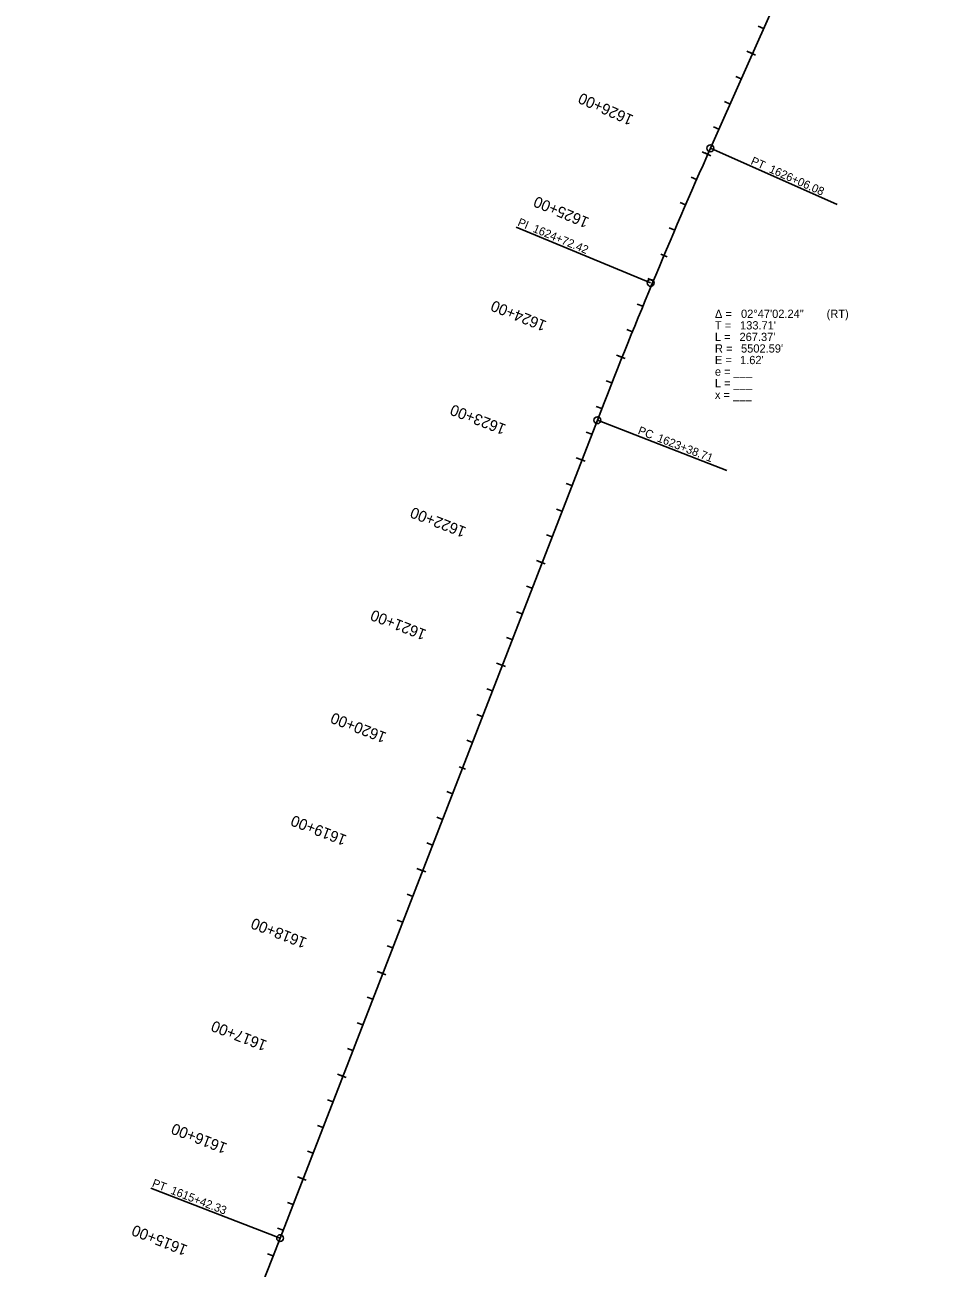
# Model space of a CAD drawing. Extents: x 14119411 to 14122090, y 8669365 to 8673150.
# Drawn here: x 14119641 to 14120466, y 8670129 to 8671257 of the extents above; entities that cross this region are included whole.
import ezdxf

# ---------------------------------------------------------------- set-up
doc = ezdxf.new("R2010")
doc.units = 0
for name, color, linetype in [('Alignment', 7, 'Continuous'), ('Default', 7, 'Continuous'), ('TextAlignment', 7, 'Continuous'), ('TextAlignmentLrg', 7, 'Continuous'), ('TextAlignmentSml', 7, 'Continuous')]:
    doc.layers.add(name, color=color, linetype=linetype)

msp = doc.modelspace()

# ---------------------------------------------------------------- linework, layer by layer
at = {"layer": 'Alignment'}
for p, q in [((14120263.5, 8671145.2), (14120465.7, 8671599.8)), ((14119873, 8670155.8), (14120160.9, 8670898.3))]:
    msp.add_line(p, q, dxfattribs=at)
for centre, radius, start, end in [((14125291.5, 8668909.5), 5502.6, 156.0273, 158.8112), ((14115436.3, 8671875.7), 4758.5, 332.0917, 338.8112)]:
    msp.add_arc(centre, radius, start, end, dxfattribs=at)
at = {"layer": 'Default'}
for p, q in [((14120263.5, 8671145.2), (14120465.7, 8671599.8)), ((14119873, 8670155.8), (14120160.9, 8670898.3)), ((14119873, 8670155.8), (14120160.9, 8670898.3))]:
    msp.add_line(p, q, dxfattribs=at)
for centre, radius, start, end in [((14125291.5, 8668909.5), 5502.6, 156.0273, 158.8112), ((14115436.3, 8671875.7), 4758.5, 332.0917, 338.8112)]:
    msp.add_arc(centre, radius, start, end, dxfattribs=at)
at = {"layer": 'TextAlignment'}
for p, q in [((14120263.5, 8671145.2), (14120378.7, 8671094)), ((14120378.7, 8671094), (14120378.7, 8671094)), ((14120209.2, 8671023), (14120087.3, 8671073.7)), ((14120087.3, 8671073.7), (14120087.3, 8671073.7)), ((14120160.9, 8670898.3), (14120278.3, 8670852.8)), ((14120278.3, 8670852.8), (14120278.3, 8670852.8)), ((14119873, 8670155.8), (14119755.5, 8670201.3)), ((14119755.5, 8670201.3), (14119755.5, 8670201.3))]:
    msp.add_line(p, q, dxfattribs=at)
for centre in [(14120263.5, 8671145.2), (14120209.2, 8671023), (14120160.9, 8670898.3), (14119873, 8670155.8)]:
    msp.add_circle(centre, 3.12, dxfattribs=at)
at = {"layer": 'TextAlignmentLrg'}
for p, q in [((14120301.7, 8671231), (14120296.7, 8671233.2)), ((14120261.1, 8671139.6), (14120256.1, 8671141.8)), ((14120218.5, 8671049), (14120224.2, 8671046.7)), ((14120183.3, 8670955.4), (14120178.3, 8670957.4)), ((14120146.9, 8670862.3), (14120141.8, 8670864.2)), ((14120110.7, 8670769), (14120105.6, 8670771)), ((14120074.6, 8670675.8), (14120069.5, 8670677.7)), ((14120035.6, 8670583.6), (14120041.3, 8670581.4)), ((14120002.3, 8670489.3), (14119997.2, 8670491.3)), ((14119966.2, 8670396.1), (14119961.1, 8670398)), ((14119930, 8670302.8), (14119924.9, 8670304.8)), ((14119893.9, 8670209.6), (14119888.8, 8670211.5))]:
    msp.add_line(p, q, dxfattribs=at)
at = {"layer": 'TextAlignmentSml'}
for p, q in [((14120311.8, 8671253.9), (14120306.9, 8671256.1)), ((14120298.9, 8671232.3), (14120304.5, 8671229.8)), ((14120291.5, 8671208.2), (14120286.5, 8671210.4)), ((14120281.4, 8671185.3), (14120276.4, 8671187.5)), ((14120271.2, 8671162.5), (14120266.2, 8671164.7)), ((14120258.3, 8671140.9), (14120263.9, 8671138.4)), ((14120251, 8671116.8), (14120246, 8671118.9)), ((14120241, 8671093.8), (14120236, 8671096)), ((14120231.1, 8671070.9), (14120226.1, 8671073)), ((14120218.5, 8671049), (14120224.2, 8671046.7)), ((14120211.7, 8671024.8), (14120206.7, 8671026.9)), ((14120202.1, 8671001.7), (14120197.1, 8671003.8)), ((14120192.7, 8670978.6), (14120187.6, 8670980.6)), ((14120180.5, 8670956.5), (14120186.2, 8670954.2)), ((14120174.1, 8670932.1), (14120169, 8670934.1)), ((14120165, 8670908.9), (14120159.9, 8670910.9)), ((14120155.9, 8670885.6), (14120150.8, 8670887.5)), ((14120144, 8670863.4), (14120149.7, 8670861.1)), ((14120137.8, 8670838.9), (14120132.7, 8670840.9)), ((14120128.8, 8670815.6), (14120123.7, 8670817.6)), ((14120119.8, 8670792.3), (14120114.7, 8670794.3)), ((14120107.9, 8670770.1), (14120113.6, 8670767.9)), ((14120101.7, 8670745.7), (14120096.6, 8670747.7)), ((14120092.7, 8670722.4), (14120087.6, 8670724.4)), ((14120083.6, 8670699.1), (14120078.5, 8670701.1)), ((14120071.7, 8670676.9), (14120077.4, 8670674.7)), ((14120065.6, 8670652.5), (14120060.5, 8670654.4)), ((14120056.5, 8670629.2), (14120051.4, 8670631.1)), ((14120047.5, 8670605.8), (14120042.4, 8670607.8)), ((14120035.6, 8670583.6), (14120041.3, 8670581.4)), ((14120029.4, 8670559.2), (14120024.3, 8670561.2)), ((14120020.4, 8670535.9), (14120015.3, 8670537.9)), ((14120011.3, 8670512.6), (14120006.2, 8670514.6)), ((14119999.4, 8670490.4), (14120005.2, 8670488.2)), ((14119993.3, 8670466), (14119988.2, 8670468)), ((14119984.2, 8670442.7), (14119979.1, 8670444.6)), ((14119975.2, 8670419.4), (14119970.1, 8670421.3)), ((14119963.3, 8670397.2), (14119969, 8670394.9)), ((14119957.1, 8670372.7), (14119952, 8670374.7)), ((14119948.1, 8670349.4), (14119943, 8670351.4)), ((14119939, 8670326.1), (14119934, 8670328.1)), ((14119927.2, 8670303.9), (14119932.9, 8670301.7)), ((14119921, 8670279.5), (14119915.9, 8670281.5)), ((14119911.9, 8670256.2), (14119906.8, 8670258.2)), ((14119902.9, 8670232.9), (14119897.8, 8670234.9)), ((14119891, 8670210.7), (14119896.7, 8670208.5)), ((14119884.8, 8670186.3), (14119879.7, 8670188.2)), ((14119875.8, 8670163), (14119870.7, 8670164.9)), ((14119866.7, 8670139.7), (14119861.6, 8670141.6))]:
    msp.add_line(p, q, dxfattribs=at)

# ---------------------------------------------------------------- texts
at = {"layer": 'TextAlignment'}
for s, rotation, p in [('PT', 336.0273, (14120299.5, 8671131)), ('1626+06.08', 336.0273, (14120316.1, 8671123.6)), ('PI ', 337.4193, (14120087.9, 8671075.2)), ('1624+72.42', 337.4193, (14120101.7, 8671069.5)), ('PC', 338.8112, (14120197.1, 8670886.1)), ('1623+38.71', 338.8112, (14120214.5, 8670879.3)), ('PT', 338.8112, (14119756.1, 8670202.9)), ('1615+42.33', 338.8112, (14119773, 8670196.3))]:
    msp.add_text(s, height=7.5, rotation=rotation, dxfattribs=at).set_placement(p)
for s, p in [('Δ = ', (14120267.6, 8670991.2)), ('02°47\'02.24"', (14120291.3, 8670991.2)), (' (RT)', (14120366.2, 8670991.2)), ('T = ', (14120267.6, 8670980.7)), ("133.71'", (14120290.4, 8670980.7)), ('L = ', (14120267.6, 8670970.2)), ("267.37'", (14120289.9, 8670970.2)), ('R = ', (14120267.6, 8670959.7)), ("5502.59'", (14120291.3, 8670959.7)), ('E = ', (14120267.6, 8670949.2)), ("1.62'", (14120290.4, 8670949.2)), ('e = ___ ', (14120267.6, 8670938.7)), ('L = ___', (14120267.6, 8670928.2)), ('x = ___', (14120267.6, 8670917.7))]:
    msp.add_text(s, height=7.5, dxfattribs=at).set_placement(p)
at = {"layer": 'TextAlignmentLrg'}
for s, rotation, p in [('1625+00', 157.1318, (14120154.2, 8671081.6)), ('1620+00', 158.8112, (14119970.3, 8670614.3)), ('1615+00', 158.3016, (14119789.7, 8670148.8))]:
    msp.add_text(s, height=10.02, rotation=rotation, dxfattribs=at).set_placement(p)
at = {"layer": 'TextAlignmentSml'}
for s, rotation, p in [('1626+00', 156.0906, (14120194.5, 8671174.6)), ('1625+00', 157.1318, (14120154.2, 8671081.6)), ('1624+00', 158.1731, (14120115.6, 8670987.9)), ('1623+00', 158.8112, (14120078.8, 8670894)), ('1622+00', 158.8112, (14120042.6, 8670800.8)), ('1621+00', 158.8112, (14120006.5, 8670707.6)), ('1620+00', 158.8112, (14119970.3, 8670614.3)), ('1619+00', 158.8112, (14119934.2, 8670521.1)), ('1618+00', 158.8112, (14119898, 8670427.8)), ('1617+00', 158.8112, (14119861.9, 8670334.6)), ('1616+00', 158.8112, (14119825.7, 8670241.4)), ('1615+00', 158.3016, (14119789.7, 8670148.8))]:
    msp.add_text(s, height=10.02, rotation=rotation, dxfattribs=at).set_placement(p)

doc.saveas('drawing.dxf')
